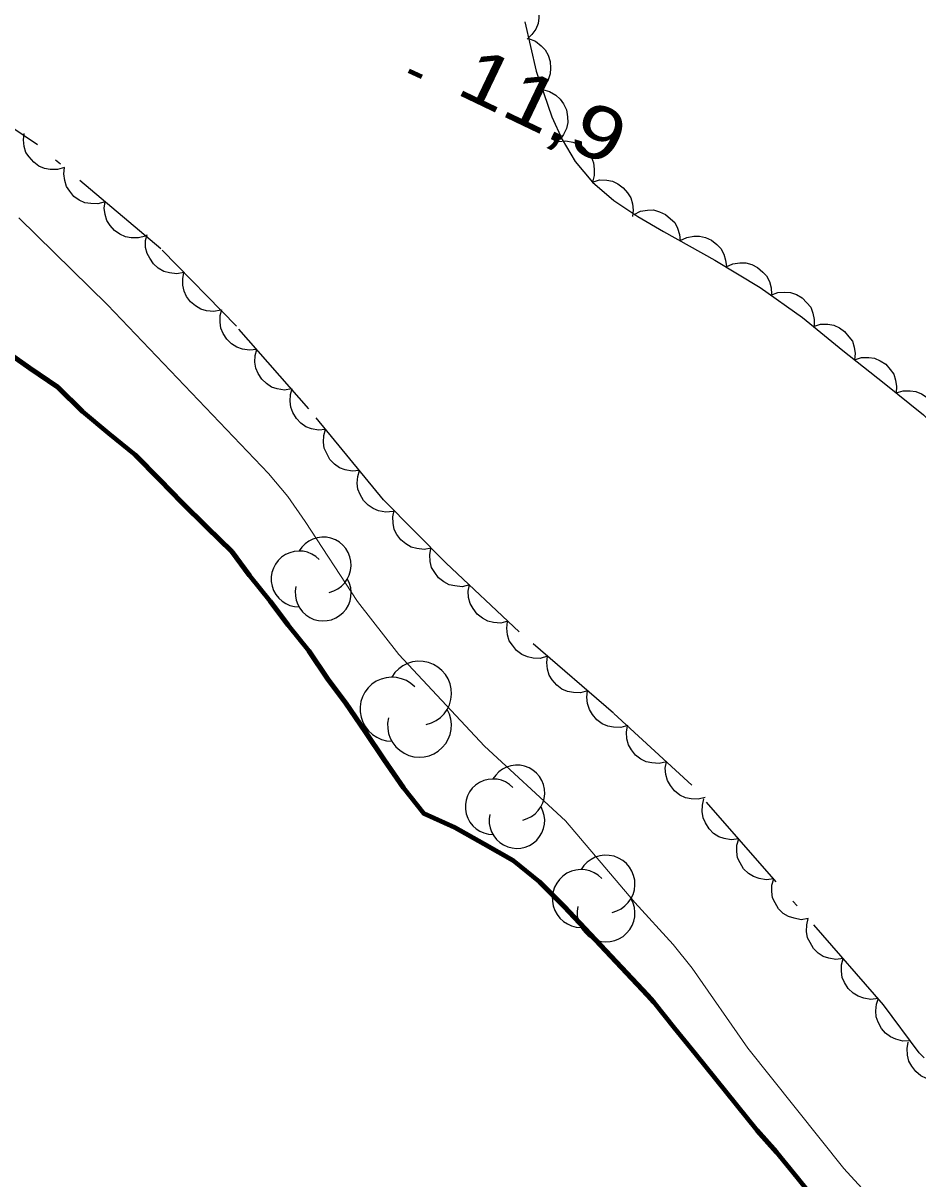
# Model space of a CAD drawing. Extents: x 355726 to 357533, y 5103782 to 5105258.
# Drawn here: x 356069.43 to 356094.78, y 5104883.01 to 5104915.74 of the extents above; entities that cross this region are included whole.
import ezdxf

# ---------------------------------------------------------------- set-up
doc = ezdxf.new("R2010")
doc.units = 0
doc.header["$LTSCALE"] = 0.6
for name, pattern in [('DASH_DOUBLE_DOT', [9.2, 5, -1.2, 0.3, -1.2, 0.3, -1.2]), ('DOT_DASHED', [7.7, 5, -1.2, 0.3, -1.2]), ('LONG_DASHED', [7.5, 6, -1.5])]:
    doc.linetypes.add(name, pattern=pattern)
for name, color, linetype, lineweight in [('2', 7, 'LONG_DASHED', 13), ('3', 7, 'Continuous', 140), ('4', 7, 'DASH_DOUBLE_DOT', 53), ('44', 7, 'Continuous', 25)]:
    doc.layers.add(name, color=color, linetype=linetype, lineweight=lineweight)

msp = doc.modelspace()

# ---------------------------------------------------------------- linework, layer by layer
at = {"layer": '2', "linetype": 'Continuous'}
msp.add_lwpolyline([(356094.52, 5104881.29), (356092.68, 5104883.3), (356089.96, 5104886.71), (356088.38, 5104888.98), (356087.84, 5104889.65), (356086.76, 5104890.84), (356084.79, 5104893.15), (356082.5, 5104895.26), (356080.07, 5104897.86), (356078.9, 5104899.36), (356077.42, 5104901.63), (356076.93, 5104902.33), (356076.38, 5104902.99), (356071.82, 5104907.76), (356069.31, 5104910.23)], dxfattribs=at)
at = {"layer": '3'}
msp.add_line((356080.36, 5104914.39), (356080.72, 5104914.22), dxfattribs=at)
at = {"layer": '4', "linetype": 'Continuous', "lineweight": 90}
msp.add_lwpolyline([(356091.94, 5104882.32), (356091.36, 5104883.05), (356090.77, 5104883.77), (356090.22, 5104884.38), (356089.64, 5104885.11), (356089.05, 5104885.83), (356088.47, 5104886.56), (356087.88, 5104887.28), (356087.3, 5104888.01), (356087.12, 5104888.21), (356084.76, 5104890.72), (356084.06, 5104891.42), (356083.31, 5104892.03), (356082.48, 5104892.5), (356081.66, 5104892.96), (356080.78, 5104893.36), (356080.2, 5104894.08), (356079.66, 5104894.88), (356079.12, 5104895.68), (356078.57, 5104896.48), (356078.06, 5104897.16), (356077.52, 5104897.96), (356076.94, 5104898.69), (356076.43, 5104899.37), (356075.84, 5104900.1), (356075.34, 5104900.78), (356074.63, 5104901.47), (356073.93, 5104902.16), (356073.3, 5104902.81), (356072.6, 5104903.51), (356071.86, 5104904.12), (356071.11, 5104904.74), (356070.41, 5104905.43), (356069.62, 5104905.97), (356068.91, 5104906.47)], dxfattribs=at)
at = {"layer": '44'}
for points in [[(356083.5, 5104916.78), (356083.69, 5104916.69), (356083.84, 5104916.55), (356083.94, 5104916.42), (356084.01, 5104916.26), (356084.05, 5104916.08), (356084.04, 5104915.89), (356084.02, 5104915.73), (356083.95, 5104915.57), (356083.84, 5104915.42), (356083.71, 5104915.29)], [(356083.75, 5104915.3), (356083.94, 5104915.23), (356084.1, 5104915.1), (356084.22, 5104914.98), (356084.3, 5104914.83), (356084.36, 5104914.65), (356084.37, 5104914.46), (356084.36, 5104914.3), (356084.3, 5104914.13), (356084.21, 5104913.97), (356084.08, 5104913.84)], [(356084.14, 5104913.86), (356084.34, 5104913.8), (356084.52, 5104913.7), (356084.64, 5104913.59), (356084.74, 5104913.45), (356084.82, 5104913.28), (356084.85, 5104913.09), (356084.86, 5104912.93), (356084.82, 5104912.76), (356084.74, 5104912.59), (356084.64, 5104912.44)], [(356070.6, 5104911.65), (356070.4, 5104911.59), (356070.2, 5104911.59), (356070.04, 5104911.62), (356069.88, 5104911.69), (356069.73, 5104911.8), (356069.6, 5104911.95), (356069.51, 5104912.08), (356069.46, 5104912.25), (356069.44, 5104912.43), (356069.46, 5104912.61)], [(356084.59, 5104912.39), (356084.8, 5104912.41), (356085, 5104912.37), (356085.15, 5104912.32), (356085.3, 5104912.22), (356085.43, 5104912.09), (356085.53, 5104911.93), (356085.59, 5104911.78), (356085.61, 5104911.6), (356085.61, 5104911.42), (356085.56, 5104911.24)], [(356071.75, 5104910.68), (356071.55, 5104910.62), (356071.35, 5104910.63), (356071.18, 5104910.65), (356071.02, 5104910.73), (356070.87, 5104910.83), (356070.75, 5104910.98), (356070.66, 5104911.11), (356070.61, 5104911.28), (356070.58, 5104911.47), (356070.6, 5104911.65)], [(356085.56, 5104911.24), (356085.76, 5104911.3), (356085.96, 5104911.29), (356086.12, 5104911.26), (356086.28, 5104911.19), (356086.43, 5104911.08), (356086.55, 5104910.93), (356086.64, 5104910.79), (356086.69, 5104910.62), (356086.71, 5104910.44), (356086.69, 5104910.26)], [(356072.9, 5104909.71), (356072.7, 5104909.66), (356072.49, 5104909.66), (356072.33, 5104909.69), (356072.17, 5104909.76), (356072.02, 5104909.87), (356071.9, 5104910.01), (356071.8, 5104910.15), (356071.75, 5104910.32), (356071.73, 5104910.5), (356071.75, 5104910.68)], [(356086.74, 5104910.32), (356086.92, 5104910.41), (356087.12, 5104910.44), (356087.29, 5104910.45), (356087.46, 5104910.4), (356087.63, 5104910.32), (356087.77, 5104910.2), (356087.89, 5104910.09), (356087.97, 5104909.93), (356088.02, 5104909.75), (356088.04, 5104909.57)], [(356073.98, 5104908.68), (356073.78, 5104908.64), (356073.58, 5104908.67), (356073.42, 5104908.71), (356073.26, 5104908.8), (356073.12, 5104908.92), (356073.02, 5104909.08), (356072.94, 5104909.22), (356072.9, 5104909.39), (356072.9, 5104909.58), (356072.94, 5104909.75)], [(356088.04, 5104909.58), (356088.23, 5104909.67), (356088.43, 5104909.71), (356088.59, 5104909.71), (356088.76, 5104909.67), (356088.93, 5104909.59), (356089.08, 5104909.47), (356089.19, 5104909.36), (356089.28, 5104909.2), (356089.33, 5104909.03), (356089.35, 5104908.85)], [(356089.34, 5104908.84), (356089.53, 5104908.92), (356089.73, 5104908.95), (356089.9, 5104908.95), (356090.07, 5104908.9), (356090.23, 5104908.82), (356090.38, 5104908.69), (356090.49, 5104908.58), (356090.57, 5104908.42), (356090.62, 5104908.24), (356090.63, 5104908.06)], [(356075.03, 5104907.61), (356074.83, 5104907.57), (356074.62, 5104907.59), (356074.46, 5104907.64), (356074.31, 5104907.73), (356074.17, 5104907.85), (356074.06, 5104908), (356073.99, 5104908.15), (356073.95, 5104908.32), (356073.95, 5104908.5), (356073.98, 5104908.68)], [(356090.61, 5104908.04), (356090.81, 5104908.11), (356091.01, 5104908.12), (356091.17, 5104908.11), (356091.34, 5104908.05), (356091.5, 5104907.96), (356091.63, 5104907.82), (356091.74, 5104907.7), (356091.8, 5104907.53), (356091.84, 5104907.35), (356091.84, 5104907.17)], [(356076.05, 5104906.5), (356075.84, 5104906.48), (356075.64, 5104906.51), (356075.48, 5104906.56), (356075.33, 5104906.66), (356075.2, 5104906.79), (356075.1, 5104906.95), (356075.03, 5104907.1), (356075.01, 5104907.27), (356075.01, 5104907.46), (356075.06, 5104907.63)], [(356091.82, 5104907.15), (356092.02, 5104907.21), (356092.22, 5104907.21), (356092.39, 5104907.19), (356092.55, 5104907.11), (356092.7, 5104907.01), (356092.82, 5104906.86), (356092.92, 5104906.73), (356092.97, 5104906.56), (356093, 5104906.38), (356092.98, 5104906.2)], [(356077.03, 5104905.38), (356076.83, 5104905.35), (356076.63, 5104905.38), (356076.47, 5104905.43), (356076.32, 5104905.53), (356076.19, 5104905.66), (356076.09, 5104905.82), (356076.02, 5104905.97), (356075.99, 5104906.14), (356076, 5104906.33), (356076.05, 5104906.5)], [(356092.98, 5104906.2), (356093.18, 5104906.27), (356093.39, 5104906.27), (356093.55, 5104906.25), (356093.71, 5104906.18), (356093.87, 5104906.08), (356093.99, 5104905.93), (356094.09, 5104905.8), (356094.14, 5104905.63), (356094.17, 5104905.45), (356094.16, 5104905.27)], [(356078, 5104904.23), (356077.8, 5104904.21), (356077.6, 5104904.25), (356077.44, 5104904.31), (356077.3, 5104904.41), (356077.17, 5104904.54), (356077.07, 5104904.71), (356077.01, 5104904.86), (356076.99, 5104905.03), (356077, 5104905.22), (356077.05, 5104905.39)], [(356094.16, 5104905.27), (356094.36, 5104905.33), (356094.56, 5104905.33), (356094.72, 5104905.31), (356094.88, 5104905.24), (356095.04, 5104905.14), (356095.17, 5104904.99), (356095.26, 5104904.86), (356095.31, 5104904.69), (356095.34, 5104904.51), (356095.33, 5104904.33)], [(356078.96, 5104903.07), (356078.75, 5104903.05), (356078.55, 5104903.09), (356078.39, 5104903.15), (356078.25, 5104903.25), (356078.12, 5104903.38), (356078.03, 5104903.55), (356077.96, 5104903.7), (356077.94, 5104903.87), (356077.95, 5104904.06), (356078, 5104904.23)], [(356079.91, 5104901.91), (356079.7, 5104901.89), (356079.5, 5104901.93), (356079.35, 5104901.99), (356079.2, 5104902.09), (356079.07, 5104902.22), (356078.98, 5104902.39), (356078.91, 5104902.54), (356078.89, 5104902.71), (356078.91, 5104902.9), (356078.96, 5104903.07)], [(356080.99, 5104900.87), (356080.79, 5104900.83), (356080.58, 5104900.86), (356080.42, 5104900.9), (356080.27, 5104900.99), (356080.13, 5104901.11), (356080.02, 5104901.26), (356079.94, 5104901.4), (356079.91, 5104901.58), (356079.9, 5104901.76), (356079.94, 5104901.94)], [(356082.07, 5104899.83), (356081.87, 5104899.78), (356081.66, 5104899.8), (356081.5, 5104899.83), (356081.35, 5104899.92), (356081.2, 5104900.03), (356081.09, 5104900.18), (356081, 5104900.32), (356080.96, 5104900.49), (356080.95, 5104900.68), (356080.98, 5104900.86)], [(356083.16, 5104898.8), (356082.96, 5104898.75), (356082.75, 5104898.77), (356082.59, 5104898.8), (356082.44, 5104898.89), (356082.29, 5104899), (356082.18, 5104899.16), (356082.09, 5104899.3), (356082.05, 5104899.47), (356082.04, 5104899.65), (356082.07, 5104899.83)], [(356084.28, 5104897.81), (356084.08, 5104897.75), (356083.88, 5104897.76), (356083.72, 5104897.79), (356083.56, 5104897.86), (356083.41, 5104897.97), (356083.29, 5104898.12), (356083.2, 5104898.25), (356083.15, 5104898.42), (356083.13, 5104898.61), (356083.15, 5104898.79)], [(356085.42, 5104896.83), (356085.22, 5104896.77), (356085.02, 5104896.78), (356084.85, 5104896.81), (356084.69, 5104896.88), (356084.55, 5104896.99), (356084.42, 5104897.14), (356084.33, 5104897.27), (356084.28, 5104897.44), (356084.26, 5104897.63), (356084.28, 5104897.81)], [(356086.56, 5104895.85), (356086.36, 5104895.79), (356086.15, 5104895.8), (356085.99, 5104895.83), (356085.83, 5104895.9), (356085.68, 5104896.01), (356085.56, 5104896.16), (356085.47, 5104896.3), (356085.42, 5104896.47), (356085.4, 5104896.65), (356085.42, 5104896.83)], [(356087.65, 5104894.82), (356087.45, 5104894.77), (356087.24, 5104894.79), (356087.08, 5104894.82), (356086.93, 5104894.9), (356086.78, 5104895.01), (356086.66, 5104895.16), (356086.58, 5104895.3), (356086.53, 5104895.47), (356086.52, 5104895.66), (356086.55, 5104895.84)], [(356088.75, 5104893.81), (356088.55, 5104893.76), (356088.35, 5104893.77), (356088.19, 5104893.8), (356088.03, 5104893.88), (356087.88, 5104894), (356087.77, 5104894.15), (356087.68, 5104894.29), (356087.64, 5104894.46), (356087.62, 5104894.64), (356087.65, 5104894.82)], [(356089.7, 5104892.64), (356089.49, 5104892.61), (356089.29, 5104892.65), (356089.14, 5104892.7), (356088.99, 5104892.79), (356088.86, 5104892.92), (356088.76, 5104893.09), (356088.69, 5104893.23), (356088.66, 5104893.41), (356088.67, 5104893.59), (356088.71, 5104893.77)], [(356090.69, 5104891.51), (356090.48, 5104891.48), (356090.28, 5104891.52), (356090.12, 5104891.57), (356089.98, 5104891.66), (356089.84, 5104891.79), (356089.74, 5104891.96), (356089.67, 5104892.1), (356089.65, 5104892.28), (356089.65, 5104892.46), (356089.7, 5104892.64)], [(356091.67, 5104890.38), (356091.47, 5104890.35), (356091.27, 5104890.39), (356091.11, 5104890.44), (356090.96, 5104890.53), (356090.83, 5104890.66), (356090.73, 5104890.83), (356090.66, 5104890.97), (356090.64, 5104891.15), (356090.64, 5104891.33), (356090.69, 5104891.51)], [(356092.66, 5104889.25), (356092.45, 5104889.22), (356092.25, 5104889.26), (356092.09, 5104889.31), (356091.95, 5104889.4), (356091.82, 5104889.53), (356091.72, 5104889.7), (356091.65, 5104889.84), (356091.62, 5104890.02), (356091.63, 5104890.2), (356091.67, 5104890.38)], [(356093.65, 5104888.12), (356093.44, 5104888.09), (356093.24, 5104888.13), (356093.08, 5104888.18), (356092.94, 5104888.27), (356092.8, 5104888.4), (356092.7, 5104888.57), (356092.63, 5104888.71), (356092.61, 5104888.89), (356092.61, 5104889.07), (356092.66, 5104889.25)], [(356094.55, 5104886.92), (356094.35, 5104886.91), (356094.15, 5104886.97), (356094, 5104887.03), (356093.86, 5104887.14), (356093.74, 5104887.27), (356093.65, 5104887.45), (356093.59, 5104887.6), (356093.58, 5104887.77), (356093.6, 5104887.96), (356093.66, 5104888.13)], [(356095.58, 5104885.84), (356095.38, 5104885.79), (356095.18, 5104885.81), (356095.02, 5104885.85), (356094.86, 5104885.93), (356094.72, 5104886.05), (356094.6, 5104886.2), (356094.52, 5104886.34), (356094.48, 5104886.51), (356094.47, 5104886.7), (356094.5, 5104886.88)]]:
    msp.add_lwpolyline(points, dxfattribs=at)
at = {"layer": '44', "linetype": 'DOT_DASHED'}
for points in [[(356083.64, 5104915.78), (356083.96, 5104914.38), (356084.41, 5104913.09), (356084.7, 5104912.44), (356085.07, 5104911.82), (356085.56, 5104911.24), (356086.16, 5104910.72), (356086.84, 5104910.26), (356087.57, 5104909.84), (356089.02, 5104909.03), (356090.31, 5104908.25), (356091.51, 5104907.4), (356092.65, 5104906.47), (356093.82, 5104905.54), (356094.93, 5104904.65), (356095.79, 5104903.8), (356096.1, 5104903.34), (356096.55, 5104902.45), (356096.69, 5104901.98), (356096.81, 5104900.95)], [(356120.95, 5104859.85), (356116.68, 5104864.23), (356113.42, 5104867.25), (356106.48, 5104875.29), (356104.86, 5104876.99), (356102.64, 5104879.03), (356098.29, 5104883.24), (356094.81, 5104886.58), (356093.8, 5104887.94), (356088.37, 5104894.16), (356086.15, 5104896.2), (356083.48, 5104898.5), (356081.41, 5104900.45), (356079.64, 5104902.24), (356077.52, 5104904.82), (356075.47, 5104907.16), (356073.33, 5104909.35), (356069.84, 5104912.29), (356068.11, 5104913.46)]]:
    msp.add_lwpolyline(points, dxfattribs=at)
at = {"layer": '44'}
for centre, radius, start, end in [((356077.931, 5104900.394), 0.792, 282.2692, 149.7263), ((356077.249, 5104899.998), 0.792, 44.1154, 269.804), ((356077.931, 5104899.602), 0.792, 166.9369, 29.6212), ((356080.658, 5104896.764), 0.906, 282.2692, 149.7263), ((356079.879, 5104896.311), 0.906, 44.1154, 269.804), ((356080.658, 5104895.858), 0.906, 166.9369, 29.6212), ((356083.418, 5104893.941), 0.786, 282.2692, 149.7263), ((356082.742, 5104893.548), 0.786, 44.1154, 269.804), ((356083.418, 5104893.155), 0.786, 166.9369, 29.6212), ((356085.942, 5104891.358), 0.819, 282.2692, 149.7263), ((356085.237, 5104890.949), 0.819, 44.1154, 269.804), ((356085.942, 5104890.539), 0.819, 166.9369, 29.6212)]:
    msp.add_arc(centre, radius, start, end, dxfattribs=at)

# ---------------------------------------------------------------- texts
at = {"layer": '3', "width": 1.25}
msp.add_text('11,9   ', height=1.5, rotation=334.423, dxfattribs=at).set_placement((356081.65, 5104913.76))

doc.saveas('drawing.dxf')
